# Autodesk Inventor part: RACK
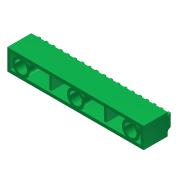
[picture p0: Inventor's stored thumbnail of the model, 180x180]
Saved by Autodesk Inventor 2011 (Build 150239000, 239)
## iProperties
Created: 2007-09
Part Number: RACK
Material: ABS Plastic
Document SubType Name: Modeling
Density: 1.06 g/cm^3
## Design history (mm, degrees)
feature "Base1"
body "Solid1"
